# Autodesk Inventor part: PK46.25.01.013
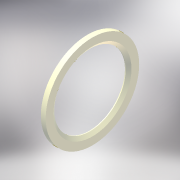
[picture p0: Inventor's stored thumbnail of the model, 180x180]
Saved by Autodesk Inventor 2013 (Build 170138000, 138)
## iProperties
Created: 2005-04
Part Number: PK46.25.01.013
Material: Nylon-6/6
Document SubType Name: Modeling
Designer: salex
Manufacturer: Standard
Standards Organization: Custom
Density: 1.13 g/cm^3
Author: salex
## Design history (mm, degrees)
sketch "Эскиз1"
  geometry: L1 (0, 0)-(22.911, 0) reference; L2 (0, 52.5)-(0, 57.5); L3 (0, 57.5)-(6, 57.5); L4 (6, 57.5)-(6, 48); L5 (6, 48)-(3, 44); L6 (3, 44)-(2, 44); L7 (2, 44)-(2, 52.5); L8 (2, 52.5)-(0, 52.5)
  constraints: 16 end point, 4 perpendicular, 2 horizontal, 2 parallel, 1 other
  dimensions: "d0" = 0 distance from line of L1.start L2; "d1" = 6 distance of L2.end L3.end; "d2" = 115 diameter of L3 L1; "d3" = 1 distance of L5.end L6.end; "d4" = 2 distance of L7.end L2.start; "d5" = 96 diameter of L4.end L1; "d6" = 105 diameter of L8 L1; "d7" = 88 diameter of L6 L1
revolve "Вращение1" sketch "Эскиз1" stored, may be unused: angle "d8" = 90 deg
body "Solid1"
